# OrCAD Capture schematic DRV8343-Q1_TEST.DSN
size A
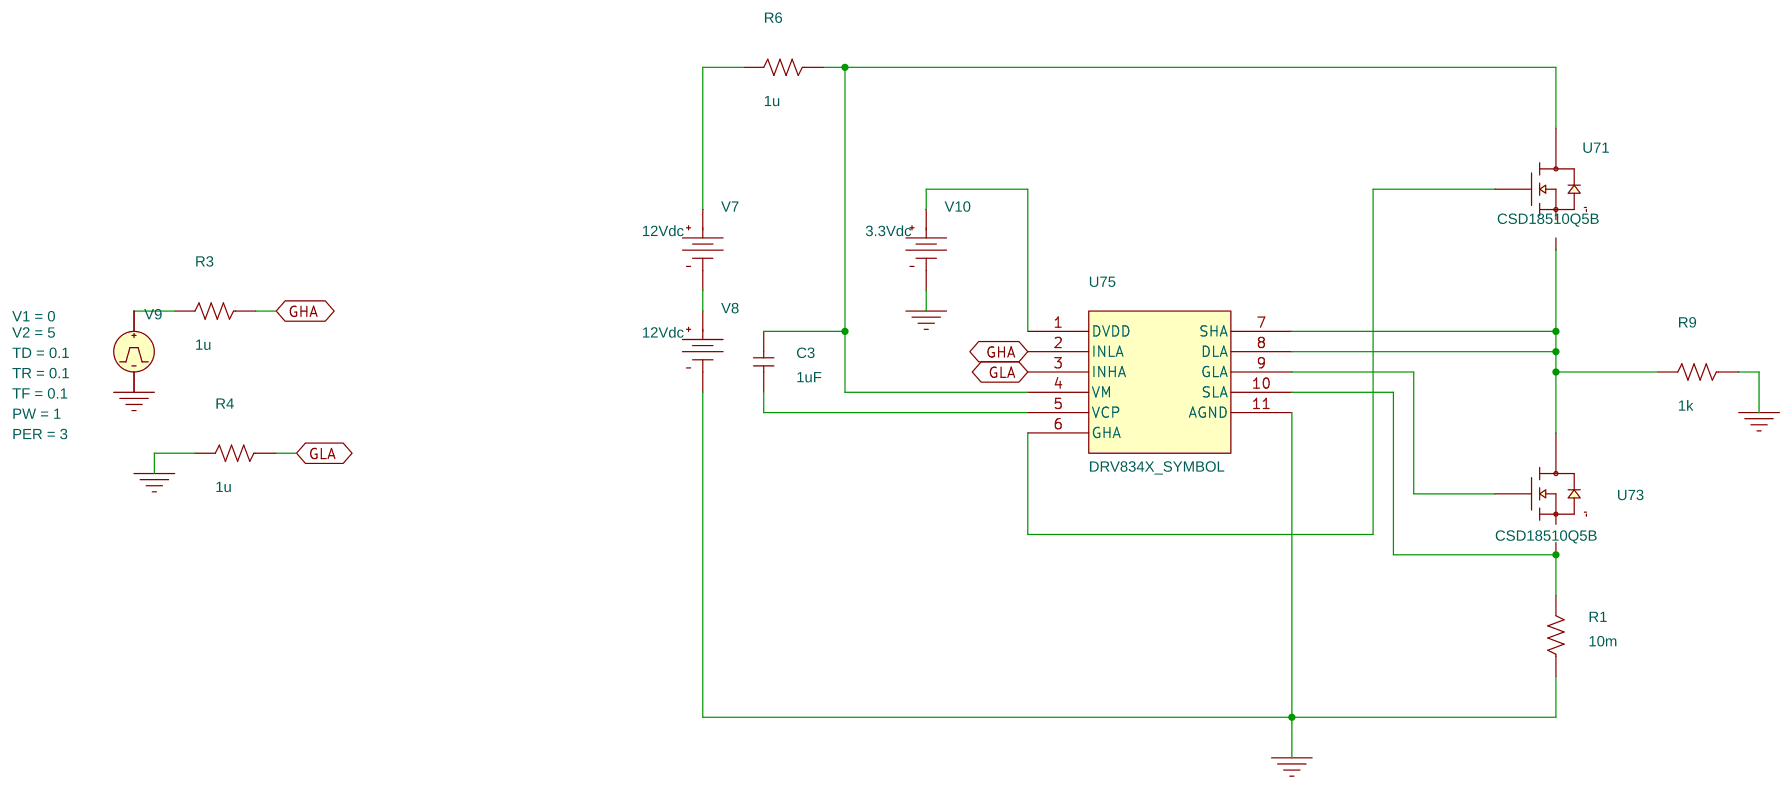
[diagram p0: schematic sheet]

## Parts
C3  1uF  [cap196]
R1  10m  [AXRC05]
R3  1u  [AXRC05]
R4  1u  [AXRC05]
R6  1u  [AXRC05]
R9  1k  [AXRC05]
U71  CSD18510Q5B
U73  CSD18510Q5B
U75  DRV834X_SYMBOL
V7  VDC
V8  VDC
V9  VPULSE
V10  VDC

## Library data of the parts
C3 = C
R1 R3 R4 R6 R9 = R
U71 U73 = CSD18510Q5B
U75 = DRV834X_SYMBOL
V7 V8 = VDC: DC: 12Vdc
V9 = VPULSE: PER: 3; PW: 1; TD: 0.1; TF: 0.1; TR: 0.1; V1: 0; V2: 5
V10 = VDC: DC: 3.3Vdc

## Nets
0: R1.1 R4.2 R9.1 U75.11(AGND) V8.1(-) V9.2(-) V10.1(-)
GHA: R3.1 U75.2(INLA)
GLA: R4.1 U75.3(INHA)
N59638: R6.2 V7.0(+)
N59646: C3.2 R6.1 U71.3(drain) U75.4(VM)
N59716: U71.2(gate) U75.6(GHA)
N59728: V7.1(-) V8.0(+)
N59794: R9.2 U71.1(source) U73.3(drain) U75.7(SHA) U75.8(DLA)
N59886: U73.2(gate) U75.9(GLA)
N59916: C3.1 U75.5(VCP)
N59924: R1.2 U73.1(source) U75.10(SLA)
N60272: R3.2 V9.1(+)
N62069: U75.1(DVDD) V10.0(+)
